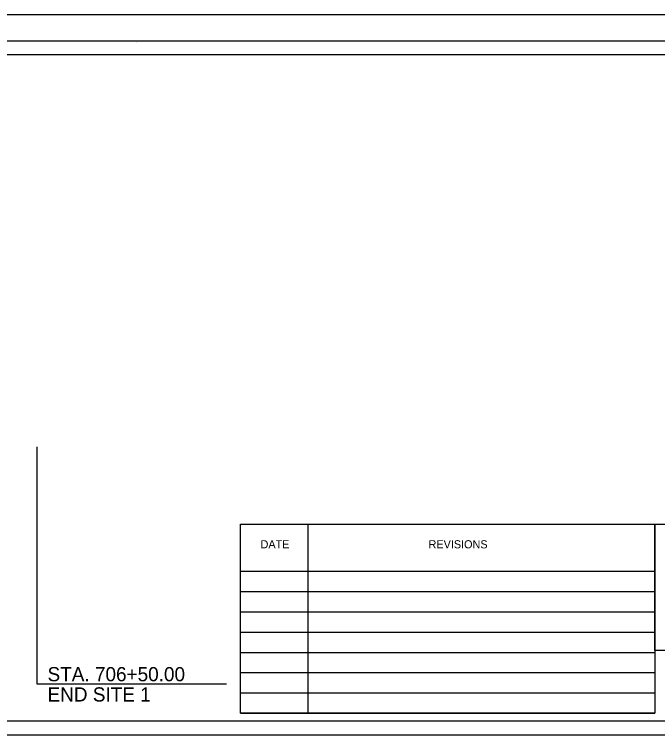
# Model space of a CAD drawing. Extents: x 814841 to 962585, y -174183 to 1802800.
# Drawn here: x 817705 to 818181, y 1802262 to 1802800 of the extents above; entities that cross this region are included whole.
import ezdxf

# ---------------------------------------------------------------- set-up
doc = ezdxf.new("R2010")
doc.units = 0
for name, color, linetype in [('Legend', 7, 'Continuous'), ('R_Border', 7, 'Continuous'), ('R_Border Notes', 7, 'Continuous'), ('R_Border Plan-Plan', 7, 'Continuous'), ('R_Detour Annot', 7, 'Continuous'), ('R_Draft', 7, 'Continuous'), ('R_No Plot', 7, 'Continuous')]:
    doc.layers.add(name, color=color, linetype=linetype)

msp = doc.modelspace()

# ---------------------------------------------------------------- linework, layer by layer
at = {"layer": 'Legend'}
msp.add_lwpolyline([(818179.3, 1802422.91), (818344.3, 1802422.91), (818344.3, 1802329.38), (818179.3, 1802329.38)], close=True, dxfattribs=at)
at = {"layer": 'R_Border'}
for p, q in [((817033.1, 1802780.6), (818614, 1802780.6)), ((817795.7, 1802779.3), (817795.7, 1802779.3)), ((817795.7, 1802779.3), (817795.7, 1802779.3))]:
    msp.add_line(p, q, dxfattribs=at)
at = {"layer": 'R_Border Notes'}
for p, q in [((817922.28, 1802422.91), (818179.3, 1802422.91)), ((817922.28, 1802422.91), (817922.28, 1802282.91)), ((817872.28, 1802387.91), (818179.3, 1802387.91)), ((817872.28, 1802372.91), (818179.3, 1802372.91)), ((817872.28, 1802357.91), (818179.3, 1802357.91)), ((817872.28, 1802342.91), (818179.3, 1802342.91)), ((817872.28, 1802327.91), (818179.3, 1802327.91)), ((817872.28, 1802312.91), (818179.3, 1802312.91)), ((817872.28, 1802297.91), (818179.3, 1802297.91)), ((817872.28, 1802282.91), (818179.3, 1802282.91))]:
    msp.add_line(p, q, dxfattribs=at)
msp.add_lwpolyline([(817872.28, 1802422.91), (818179.3, 1802422.91), (818179.3, 1802282.91), (817872.28, 1802282.91)], close=True, dxfattribs=at)
at = {"layer": 'R_Border Plan-Plan'}
msp.add_line((817033.1, 1802266.95), (818614, 1802266.95), dxfattribs=at)
at = {"layer": 'R_Draft'}
for p, q in [((817721.65, 1802304.27), (817721.65, 1802480.12)), ((817862.05, 1802304.27), (817721.65, 1802304.27))]:
    msp.add_line(p, q, dxfattribs=at)
at = {"layer": 'R_No Plot'}
for points in [[(816971.06, 1802800.08), (818637.76, 1802800.08), (818637.76, 1801733.39), (816971.06, 1801733.39)], [(818604, 1802276.95), (817043.1, 1802276.95), (817043.1, 1802770.6), (818290.8, 1802770.6), (818290.8, 1802721.2), (818378.5, 1802721.2), (818499, 1802721.2), (818499, 1802609.54), (818604, 1802609.54)], [(818604, 1802276.95), (817043.1, 1802276.95), (817043.1, 1802770.6), (818290.8, 1802770.6), (818290.8, 1802721.2), (818378.5, 1802721.2), (818499, 1802721.2), (818499, 1802609.54), (818604, 1802609.54)], [(818604, 1802276.95), (817043.1, 1802276.95), (817043.1, 1802770.6), (818290.8, 1802770.6), (818290.8, 1802721.2), (818378.5, 1802721.2), (818499, 1802721.2), (818499, 1802609.54), (818604, 1802609.54)], [(818604, 1802276.95), (817043.1, 1802276.95), (817043.1, 1802770.6), (818290.8, 1802770.6), (818290.8, 1802721.2), (818378.5, 1802721.2), (818499, 1802721.2), (818499, 1802609.54), (818604, 1802609.54)], [(818604, 1802276.95), (817043.1, 1802276.95), (817043.1, 1802770.6), (818290.8, 1802770.6), (818290.8, 1802721.2), (818378.5, 1802721.2), (818499, 1802721.2), (818499, 1802609.54), (818604, 1802609.54)], [(818604, 1802276.95), (817043.1, 1802276.95), (817043.1, 1802770.6), (818290.8, 1802770.6), (818290.8, 1802721.2), (818378.5, 1802721.2), (818499, 1802721.2), (818499, 1802609.54), (818604, 1802609.54)], [(817043.1, 1802770.6), (818290.8, 1802770.6), (818290.8, 1802721.2), (818378.5, 1802721.2), (818499, 1802721.2), (818499, 1802609.54), (818604, 1802609.54), (818604, 1801763.3), (817043.1, 1801763.3)], [(818604, 1802276.95), (817043.1, 1802276.95), (817043.1, 1802770.6), (818290.8, 1802770.6), (818290.8, 1802721.2), (818378.5, 1802721.2), (818499, 1802721.2), (818499, 1802609.54), (818604, 1802609.54)]]:
    msp.add_lwpolyline(points, close=True, dxfattribs=at)

# ---------------------------------------------------------------- texts
at = {"layer": 'Legend'}
for s, p in [('DATE', (817887.28, 1802404.91)), ('  REVISIONS', (818007.28, 1802404.91))]:
    msp.add_text(s, height=6, dxfattribs=at).set_placement(p)
at = {"layer": 'R_Detour Annot'}
for s, p in [('STA. 706+50.00', (817729.44, 1802306.52)), ('END SITE 1', (817729.44, 1802291.52))]:
    msp.add_text(s, height=10.5, dxfattribs=at).set_placement(p)

doc.saveas('drawing.dxf')
